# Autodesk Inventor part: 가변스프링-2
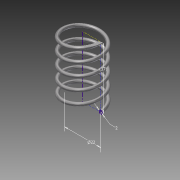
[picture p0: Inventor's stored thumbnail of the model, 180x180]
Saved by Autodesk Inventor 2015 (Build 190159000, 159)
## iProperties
Created: 2016-01
Part Number: 가변스프링-2
Material: 스테인레스 스틸
Document SubType Name: Modeling
Designer: 601-23
Density: 8 g/cm^3
Appearance: 반연마
Mass: 8.58443 g
Surface Area: 21.7229 cm^2
Volume: 1.07305 cm^3
Author: 601-23
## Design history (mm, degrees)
sketch "스케치1"
  geometry: L1 (0, 0)-(11, 0); L2 (11, 0)-(11, 36.411); L3 (11, 36.411)-(0, 36.411); L4 (0, 36.411)-(0, 0); C1 r 1 at (11, 0)
  constraints: 8 end point, 2 parallel, 1 centre point, 1 coincident, 1 horizontal, 1 perpendicular
  dimensions: "d0" = 36.4112 distance of L1.end L2.end (derived); "d1" = 22 diameter of L2 L4; "d2" = 2 diameter of C1
feature "코일1" sketch "스케치1" pitch "d3" = 5; turns "d5" = 5; dims "d4" = 36.4112 (= d0), "d6" = 0, angle "d7" = 90 deg, angle "d8" = 90 deg, "d9" = 0, "d10" = 0
node "작업 평면1"
node "작업 평면2"
sketch "스케치2"
  geometry: L1 (1, 0)-(-1, 0) reference; 1 further point
  constraints: 1 horizontal alignment
extrude "돌출1" cut sketch "스케치2" stored distance "d13" = 10; taper "d14" = 0 deg
sketch "스케치3"
  geometry: L1 (10, 0)-(12, 0) reference; 1 further point
  constraints: 1 horizontal alignment
extrude "돌출2" cut sketch "스케치3" stored distance "d15" = 10; taper "d16" = 0 deg
node "솔리드1"
node "절단 모서리 투영1"
node "절단 모서리 투영2"
other parameters: "d11" = 90 deg, "d12" = 90 deg
